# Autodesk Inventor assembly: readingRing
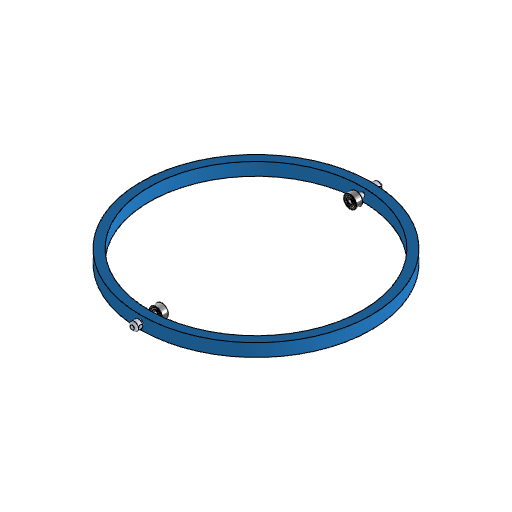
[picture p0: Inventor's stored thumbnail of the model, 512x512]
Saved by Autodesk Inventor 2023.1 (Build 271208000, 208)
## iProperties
Created: 2021-02
Part Number: readingRing
Document SubType Name: Assembly
Designer: ftrauzettel
Author: ftrauzettel
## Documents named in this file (4)
- C:\Users\Fabian\OneDrive\Delft\CPMM\Machined_Prototype\Mods\Assemblies\subAssemblies\readingRing.iam
- C:\Users\Fabian\OneDrive\Delft\CPMM\Machined_Prototype\Mods\Parts\original parts\Reading ring.ipt
- C:\Users\Fabian\OneDrive\Delft\CPMM\Machined_Prototype\Mods\Parts\original parts\Cable pin.ipt
- C:\Users\Fabian\OneDrive\Delft\CPMM\Machined_Prototype\Mods\ContentCenter\en-US\ISO 1224-1 M\ISO 1224-1 - 38 - 1 x 3 x 1.5.ipt
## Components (5 placed, 3 different names)
1. Reading ring:1 — Mate:1
2. Cable pin:1 — Mate:1, Angle:1, Mate:2, Mate:3, Flush:1
3. ISO 1224-1 (Metric) 38 - 1 x 3 x 1.5:1 — Mate:3, Flush:1
4. Cable pin:2
5. ISO 1224-1 (Metric) 38 - 1 x 3 x 1.5:2
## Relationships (5: Mate 3, Angle 1, Flush 1)
- Mate:1: Reading ring:1 ↔ Cable pin:1
- Angle:1: Cable pin:1
- Mate:2: Cable pin:1
- Mate:3: Cable pin:1 ↔ ISO 1224-1 (Metric) 38 - 1 x 3 x 1.5:1
- Flush:1: Cable pin:1 ↔ ISO 1224-1 (Metric) 38 - 1 x 3 x 1.5:1
